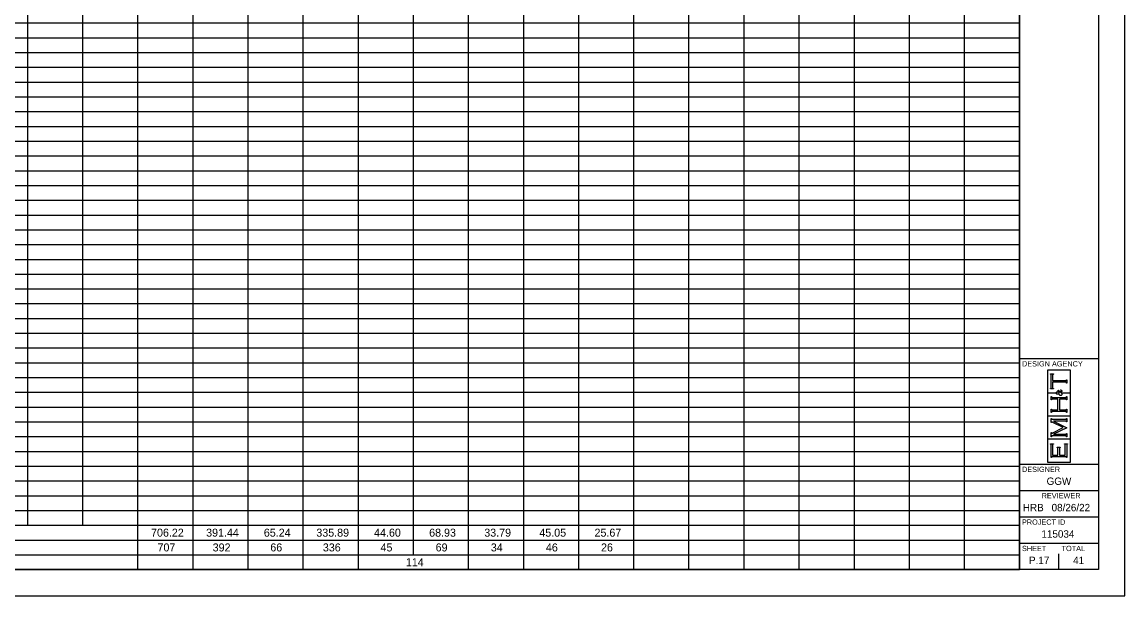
# Model space of a CAD drawing. Extents: x 0 to 34, y 0 to 22.
# Drawn here: x 13.11 to 34, y 0 to 10.88 of the extents above; entities that cross this region are included whole.
import ezdxf

# ---------------------------------------------------------------- set-up
doc = ezdxf.new("R2010")
doc.units = 0
for name, color, linetype in [('SH_Border', 7, 'Continuous'), ('SH_Cut_Line', 7, 'Continuous'), ('SH_Data', 7, 'Continuous'), ('SH_Text', 7, 'Continuous')]:
    doc.layers.add(name, color=color, linetype=linetype)

msp = doc.modelspace()

# ---------------------------------------------------------------- linework, layer by layer
at = {"layer": 'SH_Border'}
for p, q in [((32, 0.5), (32, 21.5)), ((32, 4.5), (33.5, 4.5)), ((32, 2.5), (33.5, 2.5)), ((32, 2), (33.5, 2)), ((32, 1.5), (33.5, 1.5)), ((32, 1), (33.5, 1))]:
    msp.add_line(p, q, dxfattribs=at)
msp.add_lwpolyline([(1.5, 21.5), (33.5, 21.5), (33.5, 0.5), (1.5, 0.5)], close=True, dxfattribs=at)
at = {"layer": 'SH_Cut_Line'}
msp.add_lwpolyline([(0, 0), (34, 0), (34, 22), (0, 22)], close=True, dxfattribs=at)
at = {"layer": 'SH_Data'}
for p, q in [((32.966, 4.282), (32.534, 4.282)), ((32.534, 4.282), (32.534, 3.85)), ((32.588, 4.201), (32.588, 4.208)), ((32.588, 4.208), (32.645, 4.208)), ((32.594, 4.2), (32.588, 4.201)), ((32.598, 4.198), (32.594, 4.2)), ((32.6, 4.196), (32.598, 4.198)), ((32.601, 4.193), (32.6, 4.196)), ((32.602, 4.189), (32.601, 4.193)), ((32.602, 4.183), (32.602, 4.189)), ((32.602, 3.949), (32.602, 4.183)), ((32.632, 4.193), (32.631, 4.189)), ((32.631, 4.189), (32.631, 4.183)), ((32.631, 4.183), (32.631, 4.083)), ((32.634, 4.196), (32.632, 4.193)), ((32.635, 4.198), (32.634, 4.196)), ((32.639, 4.2), (32.635, 4.198)), ((32.645, 4.201), (32.639, 4.2)), ((32.645, 4.208), (32.645, 4.201)), ((32.966, 3.85), (32.966, 4.282)), ((32.631, 4.083), (32.872, 4.083)), ((32.872, 4.049), (32.631, 4.049)), ((32.631, 4.049), (32.631, 3.949)), ((32.872, 4.083), (32.878, 4.083)), ((32.879, 4.049), (32.872, 4.049)), ((32.878, 4.083), (32.883, 4.084)), ((32.883, 4.048), (32.879, 4.049)), ((32.883, 4.084), (32.885, 4.086)), ((32.885, 4.046), (32.883, 4.048)), ((32.885, 4.086), (32.888, 4.087)), ((32.888, 4.044), (32.885, 4.046)), ((32.888, 4.087), (32.89, 4.091)), ((32.89, 4.041), (32.888, 4.044)), ((32.89, 4.091), (32.891, 4.097)), ((32.891, 4.035), (32.89, 4.041)), ((32.891, 4.097), (32.898, 4.097)), ((32.898, 4.035), (32.891, 4.035)), ((32.898, 4.097), (32.898, 4.035)), ((32.534, 3.85), (32.693, 3.85)), ((32.693, 3.844), (32.534, 3.844)), ((32.534, 3.844), (32.534, 3.412)), ((32.588, 3.93), (32.594, 3.932)), ((32.588, 3.923), (32.588, 3.93)), ((32.645, 3.923), (32.588, 3.923)), ((32.594, 3.932), (32.598, 3.934)), ((32.598, 3.934), (32.6, 3.936)), ((32.6, 3.936), (32.601, 3.939)), ((32.601, 3.939), (32.602, 3.943)), ((32.602, 3.943), (32.602, 3.949)), ((32.602, 3.716), (32.602, 3.778)), ((32.602, 3.778), (32.609, 3.778)), ((32.609, 3.778), (32.611, 3.772)), ((32.611, 3.772), (32.613, 3.768)), ((32.613, 3.768), (32.615, 3.767)), ((32.615, 3.767), (32.618, 3.765)), ((32.618, 3.765), (32.622, 3.764)), ((32.622, 3.764), (32.628, 3.764)), ((32.628, 3.764), (32.872, 3.764)), ((32.631, 3.949), (32.631, 3.943)), ((32.631, 3.943), (32.632, 3.939)), ((32.632, 3.939), (32.634, 3.936)), ((32.634, 3.936), (32.635, 3.934)), ((32.635, 3.934), (32.639, 3.932)), ((32.639, 3.932), (32.645, 3.93)), ((32.645, 3.93), (32.645, 3.923)), ((32.693, 3.85), (32.693, 3.844)), ((32.701, 3.854), (32.703, 3.859)), ((32.701, 3.848), (32.701, 3.854)), ((32.701, 3.842), (32.701, 3.848)), ((32.703, 3.837), (32.701, 3.842)), ((32.703, 3.859), (32.706, 3.862)), ((32.706, 3.832), (32.703, 3.837)), ((32.706, 3.862), (32.71, 3.866)), ((32.711, 3.826), (32.706, 3.832)), ((32.71, 3.866), (32.714, 3.868)), ((32.717, 3.823), (32.711, 3.826)), ((32.714, 3.868), (32.719, 3.868)), ((32.725, 3.823), (32.717, 3.823)), ((32.719, 3.868), (32.724, 3.868)), ((32.724, 3.868), (32.728, 3.866)), ((32.728, 3.823), (32.725, 3.823)), ((32.728, 3.866), (32.732, 3.863)), ((32.731, 3.824), (32.728, 3.823)), ((32.734, 3.824), (32.731, 3.824)), ((32.732, 3.863), (32.736, 3.859)), ((32.738, 3.825), (32.734, 3.824)), ((32.736, 3.859), (32.74, 3.853)), ((32.738, 3.869), (32.738, 3.9)), ((32.738, 3.9), (32.741, 3.9)), ((32.741, 3.869), (32.738, 3.869)), ((32.742, 3.827), (32.738, 3.825)), ((32.74, 3.853), (32.745, 3.844)), ((32.741, 3.9), (32.741, 3.896)), ((32.741, 3.896), (32.742, 3.893)), ((32.742, 3.873), (32.741, 3.871)), ((32.741, 3.871), (32.741, 3.869)), ((32.742, 3.893), (32.744, 3.891)), ((32.743, 3.874), (32.742, 3.873)), ((32.747, 3.829), (32.742, 3.827)), ((32.745, 3.875), (32.743, 3.874)), ((32.744, 3.891), (32.745, 3.889)), ((32.745, 3.889), (32.75, 3.885)), ((32.747, 3.876), (32.745, 3.875)), ((32.745, 3.844), (32.756, 3.85)), ((32.749, 3.876), (32.747, 3.876)), ((32.753, 3.817), (32.747, 3.829)), ((32.756, 3.876), (32.749, 3.876)), ((32.75, 3.885), (32.758, 3.881)), ((32.759, 3.81), (32.753, 3.817)), ((32.765, 3.872), (32.756, 3.876)), ((32.756, 3.85), (32.766, 3.857)), ((32.758, 3.881), (32.765, 3.877)), ((32.765, 3.805), (32.759, 3.81)), ((32.765, 3.877), (32.772, 3.872)), ((32.775, 3.863), (32.765, 3.872)), ((32.77, 3.801), (32.765, 3.805)), ((32.766, 3.857), (32.775, 3.863)), ((32.776, 3.799), (32.77, 3.801)), ((32.772, 3.872), (32.779, 3.867)), ((32.782, 3.799), (32.776, 3.799)), ((32.779, 3.867), (32.784, 3.871)), ((32.782, 3.902), (32.784, 3.904)), ((32.785, 3.901), (32.782, 3.902)), ((32.788, 3.799), (32.782, 3.799)), ((32.784, 3.904), (32.79, 3.903)), ((32.784, 3.871), (32.787, 3.875)), ((32.788, 3.899), (32.785, 3.901)), ((32.787, 3.875), (32.789, 3.878)), ((32.79, 3.897), (32.788, 3.899)), ((32.793, 3.802), (32.788, 3.799)), ((32.789, 3.878), (32.791, 3.882)), ((32.795, 3.861), (32.789, 3.857)), ((32.789, 3.857), (32.795, 3.851)), ((32.79, 3.903), (32.795, 3.9)), ((32.791, 3.894), (32.79, 3.897)), ((32.792, 3.892), (32.791, 3.894)), ((32.791, 3.882), (32.792, 3.885)), ((32.792, 3.888), (32.792, 3.892)), ((32.792, 3.885), (32.792, 3.888)), ((32.797, 3.806), (32.793, 3.802)), ((32.795, 3.9), (32.799, 3.896)), ((32.798, 3.866), (32.795, 3.861)), ((32.795, 3.851), (32.798, 3.845)), ((32.802, 3.811), (32.797, 3.806)), ((32.8, 3.87), (32.798, 3.866)), ((32.798, 3.845), (32.801, 3.841)), ((32.799, 3.896), (32.802, 3.892)), ((32.803, 3.874), (32.8, 3.87)), ((32.801, 3.841), (32.803, 3.836)), ((32.802, 3.892), (32.804, 3.887)), ((32.804, 3.817), (32.802, 3.811)), ((32.804, 3.878), (32.803, 3.874)), ((32.807, 3.844), (32.803, 3.85)), ((32.803, 3.85), (32.966, 3.85)), ((32.803, 3.836), (32.804, 3.831)), ((32.804, 3.887), (32.804, 3.882)), ((32.804, 3.882), (32.804, 3.878)), ((32.804, 3.831), (32.804, 3.825)), ((32.804, 3.825), (32.804, 3.817)), ((32.966, 3.844), (32.807, 3.844)), ((32.872, 3.764), (32.878, 3.764)), ((32.878, 3.764), (32.883, 3.765)), ((32.883, 3.765), (32.885, 3.767)), ((32.885, 3.767), (32.888, 3.768)), ((32.888, 3.768), (32.89, 3.772)), ((32.89, 3.772), (32.891, 3.778)), ((32.891, 3.778), (32.898, 3.778)), ((32.898, 3.778), (32.898, 3.716)), ((32.966, 3.412), (32.966, 3.844)), ((32.609, 3.716), (32.602, 3.716)), ((32.611, 3.721), (32.609, 3.716)), ((32.612, 3.725), (32.611, 3.721)), ((32.615, 3.727), (32.612, 3.725)), ((32.617, 3.729), (32.615, 3.727)), ((32.622, 3.73), (32.617, 3.729)), ((32.628, 3.73), (32.622, 3.73)), ((32.732, 3.73), (32.628, 3.73)), ((32.732, 3.527), (32.732, 3.73)), ((32.872, 3.73), (32.76, 3.73)), ((32.76, 3.73), (32.76, 3.527)), ((32.879, 3.73), (32.872, 3.73)), ((32.883, 3.729), (32.879, 3.73)), ((32.885, 3.727), (32.883, 3.729)), ((32.888, 3.725), (32.885, 3.727)), ((32.89, 3.721), (32.888, 3.725)), ((32.891, 3.716), (32.89, 3.721)), ((32.898, 3.716), (32.891, 3.716)), ((32.534, 3.412), (32.966, 3.412)), ((32.966, 3.407), (32.534, 3.407)), ((32.534, 3.407), (32.534, 2.975)), ((32.602, 3.479), (32.602, 3.54)), ((32.602, 3.54), (32.609, 3.54)), ((32.609, 3.479), (32.602, 3.479)), ((32.602, 3.285), (32.602, 3.362)), ((32.602, 3.362), (32.609, 3.362)), ((32.609, 3.54), (32.611, 3.535)), ((32.611, 3.484), (32.609, 3.479)), ((32.609, 3.362), (32.611, 3.356)), ((32.611, 3.535), (32.613, 3.531)), ((32.612, 3.488), (32.611, 3.484)), ((32.611, 3.356), (32.613, 3.353)), ((32.615, 3.49), (32.612, 3.488)), ((32.613, 3.531), (32.615, 3.529)), ((32.613, 3.353), (32.615, 3.351)), ((32.615, 3.529), (32.618, 3.528)), ((32.617, 3.492), (32.615, 3.49)), ((32.615, 3.351), (32.618, 3.349)), ((32.622, 3.493), (32.617, 3.492)), ((32.618, 3.528), (32.622, 3.527)), ((32.618, 3.349), (32.622, 3.348)), ((32.622, 3.527), (32.628, 3.527)), ((32.628, 3.493), (32.622, 3.493)), ((32.622, 3.348), (32.628, 3.348)), ((32.628, 3.527), (32.732, 3.527)), ((32.872, 3.493), (32.628, 3.493)), ((32.628, 3.348), (32.872, 3.348)), ((32.75, 3.5), (32.75, 3.5)), ((32.76, 3.527), (32.872, 3.527)), ((32.872, 3.527), (32.879, 3.527)), ((32.879, 3.493), (32.872, 3.493)), ((32.872, 3.348), (32.878, 3.348)), ((32.878, 3.348), (32.883, 3.349)), ((32.879, 3.527), (32.883, 3.527)), ((32.883, 3.492), (32.879, 3.493)), ((32.883, 3.527), (32.885, 3.529)), ((32.885, 3.49), (32.883, 3.492)), ((32.883, 3.349), (32.885, 3.351)), ((32.885, 3.529), (32.888, 3.531)), ((32.888, 3.488), (32.885, 3.49)), ((32.885, 3.351), (32.888, 3.353)), ((32.888, 3.531), (32.89, 3.535)), ((32.89, 3.484), (32.888, 3.488)), ((32.888, 3.353), (32.89, 3.356)), ((32.89, 3.535), (32.891, 3.54)), ((32.891, 3.479), (32.89, 3.484)), ((32.89, 3.356), (32.891, 3.362)), ((32.891, 3.54), (32.898, 3.54)), ((32.898, 3.479), (32.891, 3.479)), ((32.891, 3.362), (32.898, 3.362)), ((32.898, 3.54), (32.898, 3.479)), ((32.898, 3.362), (32.898, 3.3)), ((32.966, 2.975), (32.966, 3.407)), ((32.609, 3.285), (32.602, 3.285)), ((32.612, 3.292), (32.609, 3.285)), ((32.615, 3.295), (32.612, 3.292)), ((32.619, 3.295), (32.615, 3.295)), ((32.621, 3.295), (32.619, 3.295)), ((32.626, 3.294), (32.621, 3.295)), ((32.633, 3.29), (32.626, 3.294)), ((32.831, 3.191), (32.633, 3.29)), ((32.635, 3.092), (32.831, 3.191)), ((32.872, 3.314), (32.649, 3.314)), ((32.649, 3.314), (32.898, 3.188)), ((32.898, 3.188), (32.649, 3.064)), ((32.878, 3.314), (32.872, 3.314)), ((32.883, 3.313), (32.878, 3.314)), ((32.885, 3.312), (32.883, 3.313)), ((32.888, 3.31), (32.885, 3.312)), ((32.89, 3.306), (32.888, 3.31)), ((32.891, 3.3), (32.89, 3.306)), ((32.898, 3.3), (32.891, 3.3)), ((32.534, 2.975), (32.966, 2.975)), ((32.966, 2.969), (32.534, 2.969)), ((32.534, 2.969), (32.534, 2.537)), ((32.602, 3.019), (32.602, 3.096)), ((32.602, 3.096), (32.609, 3.096)), ((32.609, 3.019), (32.602, 3.019)), ((32.609, 3.096), (32.612, 3.089)), ((32.611, 3.025), (32.609, 3.019)), ((32.612, 3.028), (32.611, 3.025)), ((32.612, 3.089), (32.615, 3.085)), ((32.615, 3.03), (32.612, 3.028)), ((32.615, 3.085), (32.618, 3.085)), ((32.617, 3.032), (32.615, 3.03)), ((32.622, 3.033), (32.617, 3.032)), ((32.618, 3.085), (32.62, 3.085)), ((32.62, 3.085), (32.626, 3.088)), ((32.628, 3.033), (32.622, 3.033)), ((32.626, 3.088), (32.635, 3.092)), ((32.872, 3.033), (32.628, 3.033)), ((32.649, 3.064), (32.872, 3.064)), ((32.872, 3.064), (32.878, 3.064)), ((32.879, 3.033), (32.872, 3.033)), ((32.878, 3.064), (32.883, 3.065)), ((32.883, 3.032), (32.879, 3.033)), ((32.883, 3.065), (32.885, 3.067)), ((32.885, 3.03), (32.883, 3.032)), ((32.885, 3.067), (32.888, 3.069)), ((32.888, 3.028), (32.885, 3.03)), ((32.888, 3.069), (32.89, 3.072)), ((32.89, 3.025), (32.888, 3.028)), ((32.89, 3.072), (32.891, 3.078)), ((32.891, 3.019), (32.89, 3.025)), ((32.891, 3.078), (32.898, 3.078)), ((32.898, 3.019), (32.891, 3.019)), ((32.898, 3.078), (32.898, 3.019)), ((32.966, 2.537), (32.966, 2.969)), ((32.588, 2.876), (32.588, 2.883)), ((32.588, 2.883), (32.645, 2.883)), ((32.594, 2.875), (32.588, 2.876)), ((32.598, 2.873), (32.594, 2.875)), ((32.6, 2.87), (32.598, 2.873)), ((32.601, 2.868), (32.6, 2.87)), ((32.602, 2.864), (32.601, 2.868)), ((32.602, 2.858), (32.602, 2.864)), ((32.602, 2.623), (32.602, 2.858)), ((32.632, 2.868), (32.631, 2.864)), ((32.631, 2.864), (32.631, 2.858)), ((32.631, 2.858), (32.631, 2.671)), ((32.634, 2.87), (32.632, 2.868)), ((32.636, 2.873), (32.634, 2.87)), ((32.639, 2.875), (32.636, 2.873)), ((32.645, 2.876), (32.639, 2.875)), ((32.645, 2.883), (32.645, 2.876)), ((32.718, 2.812), (32.718, 2.818)), ((32.718, 2.818), (32.774, 2.818)), ((32.723, 2.81), (32.718, 2.812)), ((32.727, 2.808), (32.723, 2.81)), ((32.729, 2.806), (32.727, 2.808)), ((32.731, 2.803), (32.729, 2.806)), ((32.732, 2.799), (32.731, 2.803)), ((32.732, 2.793), (32.732, 2.799)), ((32.732, 2.671), (32.732, 2.793)), ((32.761, 2.803), (32.76, 2.799)), ((32.76, 2.799), (32.76, 2.793)), ((32.76, 2.793), (32.76, 2.671)), ((32.763, 2.806), (32.761, 2.803)), ((32.765, 2.808), (32.763, 2.806)), ((32.769, 2.81), (32.765, 2.808)), ((32.774, 2.812), (32.769, 2.81)), ((32.774, 2.818), (32.774, 2.812)), ((32.856, 2.879), (32.856, 2.886)), ((32.856, 2.886), (32.912, 2.886)), ((32.861, 2.878), (32.856, 2.879)), ((32.865, 2.876), (32.861, 2.878)), ((32.867, 2.874), (32.865, 2.876)), ((32.869, 2.871), (32.867, 2.874)), ((32.87, 2.867), (32.869, 2.871)), ((32.87, 2.861), (32.87, 2.867)), ((32.87, 2.671), (32.87, 2.861)), ((32.899, 2.871), (32.898, 2.867)), ((32.898, 2.867), (32.898, 2.86)), ((32.898, 2.86), (32.898, 2.623)), ((32.901, 2.873), (32.899, 2.871)), ((32.903, 2.876), (32.901, 2.873)), ((32.906, 2.878), (32.903, 2.876)), ((32.912, 2.879), (32.906, 2.878)), ((32.912, 2.886), (32.912, 2.879)), ((32.534, 2.537), (32.966, 2.537)), ((32.609, 2.623), (32.602, 2.623)), ((32.611, 2.628), (32.609, 2.623)), ((32.613, 2.632), (32.611, 2.628)), ((32.615, 2.634), (32.613, 2.632)), ((32.618, 2.636), (32.615, 2.634)), ((32.622, 2.637), (32.618, 2.636)), ((32.628, 2.637), (32.622, 2.637)), ((32.872, 2.637), (32.628, 2.637)), ((32.631, 2.671), (32.732, 2.671)), ((32.76, 2.671), (32.87, 2.671)), ((32.879, 2.637), (32.872, 2.637)), ((32.883, 2.636), (32.879, 2.637)), ((32.885, 2.634), (32.883, 2.636)), ((32.888, 2.632), (32.885, 2.634)), ((32.89, 2.628), (32.888, 2.632)), ((32.891, 2.623), (32.89, 2.628)), ((32.898, 2.623), (32.891, 2.623)), ((32.375, 0.675), (32.375, 0.675)), ((32.75, 0.5), (32.75, 0.8))]:
    msp.add_line(p, q, dxfattribs=at)
at = {"layer": 'SH_Text'}
for p, q in [((13.212, 21.5), (13.212, 1.34)), ((14.256, 21.5), (14.256, 1.34)), ((15.299, 21.5), (15.299, 0.5)), ((16.343, 21.5), (16.343, 0.5)), ((17.387, 21.5), (17.387, 0.5)), ((18.431, 21.5), (18.431, 0.5)), ((19.475, 21.5), (19.475, 0.5)), ((20.518, 21.5), (20.518, 0.78)), ((21.562, 21.5), (21.562, 0.5)), ((22.606, 21.5), (22.606, 0.5)), ((23.65, 21.5), (23.65, 0.5)), ((24.694, 21.5), (24.694, 0.5)), ((25.737, 21.5), (25.737, 0.5)), ((26.781, 21.5), (26.781, 0.5)), ((27.825, 21.5), (27.825, 0.5)), ((28.869, 21.5), (28.869, 0.5)), ((29.912, 21.5), (29.912, 0.5)), ((30.956, 21.5), (30.956, 0.5)), ((32, 21.5), (32, 0.5)), ((1.5, 10.86), (32, 10.86)), ((1.5, 10.58), (32, 10.58)), ((1.5, 10.3), (32, 10.3)), ((1.5, 10.02), (32, 10.02)), ((1.5, 9.74), (32, 9.74)), ((1.5, 9.46), (32, 9.46)), ((1.5, 9.18), (32, 9.18)), ((1.5, 8.9), (32, 8.9)), ((1.5, 8.62), (32, 8.62)), ((1.5, 8.34), (32, 8.34)), ((1.5, 8.06), (32, 8.06)), ((1.5, 7.78), (32, 7.78)), ((1.5, 7.5), (32, 7.5)), ((1.5, 7.22), (32, 7.22)), ((1.5, 6.94), (32, 6.94)), ((1.5, 6.66), (32, 6.66)), ((1.5, 6.38), (32, 6.38)), ((1.5, 6.1), (32, 6.1)), ((1.5, 5.82), (32, 5.82)), ((1.5, 5.54), (32, 5.54)), ((1.5, 5.26), (32, 5.26)), ((1.5, 4.98), (32, 4.98)), ((1.5, 4.7), (32, 4.7)), ((1.5, 4.42), (32, 4.42)), ((1.5, 4.14), (32, 4.14)), ((1.5, 3.86), (32, 3.86)), ((1.5, 3.58), (32, 3.58)), ((1.5, 3.3), (32, 3.3)), ((1.5, 3.02), (32, 3.02)), ((1.5, 2.74), (32, 2.74)), ((1.5, 2.46), (32, 2.46)), ((1.5, 2.18), (32, 2.18)), ((1.5, 1.9), (32, 1.9)), ((1.5, 1.62), (32, 1.62)), ((1.5, 1.34), (32, 1.34)), ((1.5, 1.06), (32, 1.06)), ((1.5, 0.78), (32, 0.78)), ((1.5, 0.5), (32, 0.5))]:
    msp.add_line(p, q, dxfattribs=at)

# ---------------------------------------------------------------- texts
at = {"layer": 'SH_Data'}
for s, height, p in [('DESIGN AGENCY', 0.1, (32.05, 4.35)), ('DESIGNER', 0.1, (32.05, 2.35)), ('GGW', 0.14, (32.516, 2.105)), ('REVIEWER', 0.1, (32.422, 1.85)), ('HRB', 0.14, (32.066, 1.605)), ('08/26/22', 0.14, (32.611, 1.605)), ('PROJECT ID', 0.1, (32.05, 1.35)), ('115034', 0.14, (32.418, 1.105)), ('SHEET', 0.1, (32.05, 0.85)), ('TOTAL', 0.1, (32.8, 0.85)), ('P.17', 0.14, (32.183, 0.605)), ('41', 0.14, (33.019, 0.605))]:
    msp.add_text(s, height=height, dxfattribs=at).set_placement(p)
at = {"layer": 'SH_Text'}
for s, p in [('706.22', (15.555, 1.124)), ('391.44', (16.598, 1.124)), ('65.24', (17.691, 1.124)), ('335.89', (18.685, 1.124)), ('44.60', (19.779, 1.124)), ('68.93', (20.822, 1.124)), ('33.79', (21.866, 1.124)), ('45.05', (22.909, 1.124)), ('25.67', (23.954, 1.124)), ('707', (15.677, 0.844)), ('392', (16.722, 0.844)), ('66', (17.814, 0.844)), ('336', (18.809, 0.844)), ('45', (19.901, 0.844)), ('69', (20.945, 0.844)), ('34', (21.99, 0.844)), ('46', (23.033, 0.844)), ('26', (24.077, 0.844)), ('114', (20.381, 0.564))]:
    msp.add_text(s, height=0.1515, dxfattribs=at).set_placement(p)

doc.saveas('drawing.dxf')
